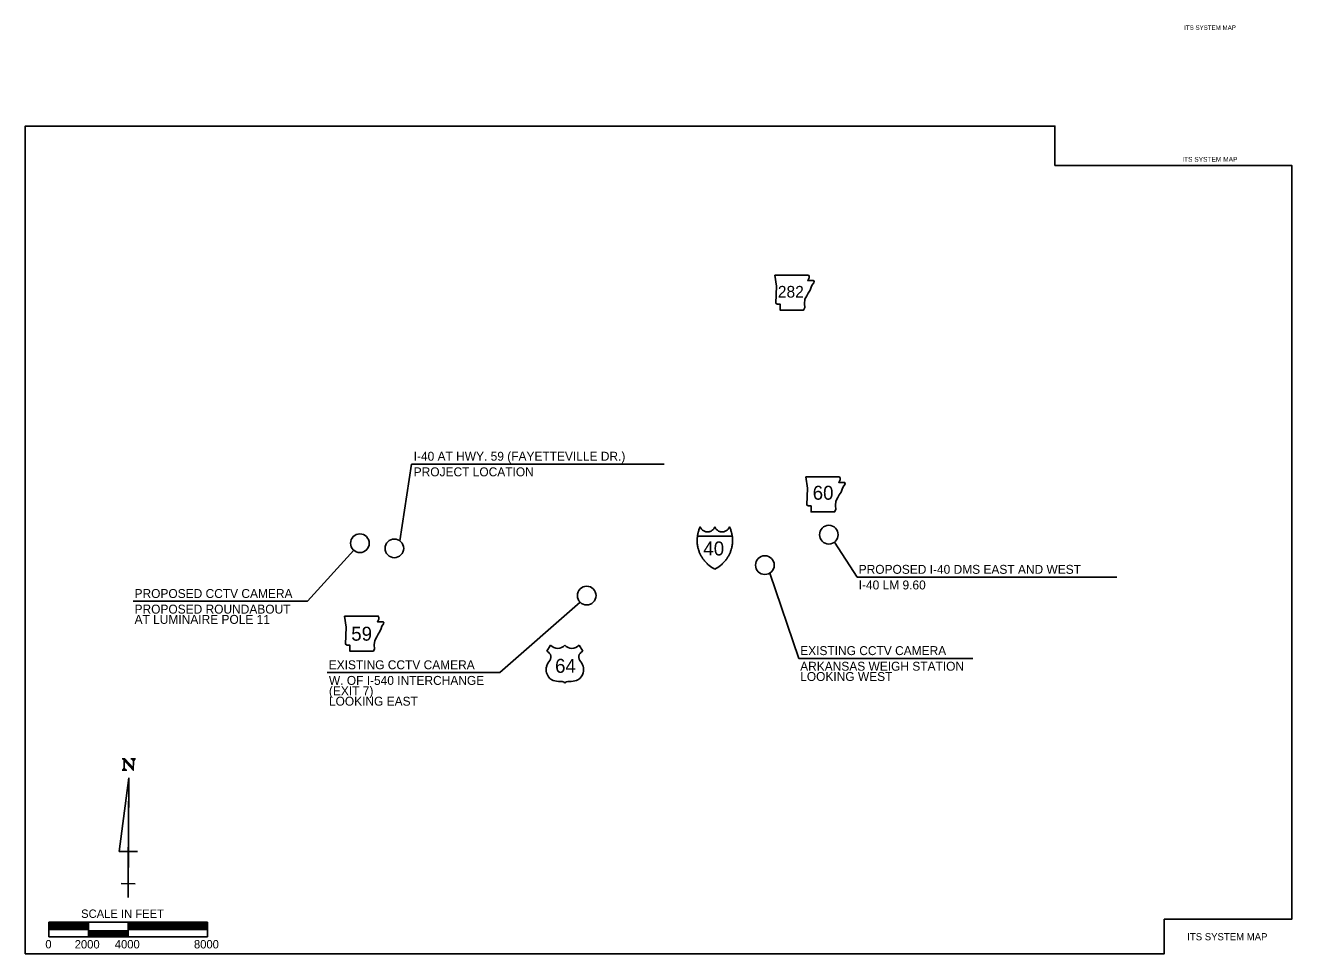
# Model space of a CAD drawing. Extents: x 164834 to 228648, y 1232466 to 1279237.
import ezdxf

# ---------------------------------------------------------------- set-up
doc = ezdxf.new("R2010")
doc.units = 0
for name, color, linetype in [('10', 7, 'Continuous'), ('G-ANNO-TEXT', 7, 'Continuous'), ('Level 1', 7, 'Continuous'), ('Level 21', 7, 'Continuous'), ('Level 22', 7, 'Continuous'), ('Level 23', 7, 'Continuous'), ('R_No Plot', 7, 'Continuous'), ('SCALE', 7, 'Continuous')]:
    doc.layers.add(name, color=color, linetype=linetype)

msp = doc.modelspace()

# ---------------------------------------------------------------- linework, layer by layer
at = {"layer": '10'}
for p, q in [((183699, 1253272), (184299, 1257133)), ((184287, 1257133), (197031, 1257133)), ((179045, 1250218), (181386, 1252788)), ((205603, 1253197), (206745, 1251435)), ((202352, 1251642), (203811, 1247341)), ((206745, 1251435), (219837, 1251436)), ((170268, 1250218), (179045, 1250218)), ((192794, 1250171), (188749, 1246626)), ((203811, 1247341), (212588, 1247341)), ((180049, 1246626), (188749, 1246626))]:
    msp.add_line(p, q, dxfattribs=at)
for centre in [(205324, 1253576), (181694, 1253144), (183430, 1252886), (202101, 1252040), (193123, 1250507)]:
    msp.add_circle(centre, 471, dxfattribs=at)
at = {"layer": 'Level 1'}
for p, q in [((170044, 1241326), (169562, 1237618)), ((170015, 1235296), (170044, 1241326)), ((170044, 1241326), (170021, 1236687)), ((169562, 1237618), (170490, 1237613)), ((170015, 1235296), (170021, 1236687)), ((170018, 1235992), (169670, 1235994)), ((169670, 1235994), (170366, 1235990)), ((170015, 1235296), (170018, 1235992))]:
    msp.add_line(p, q, dxfattribs=at)
for points in [[(169709, 1242277), (169848, 1242276), (170277, 1241807)], [(169819, 1242203), (169817, 1241809), (169750, 1241714)], [(169753, 1242276), (170276, 1241711), (170279, 1242179), (170345, 1242273)], [(169804, 1242276), (170276, 1241763)], [(169826, 1242276), (170277, 1241792)], [(170148, 1242274), (170389, 1242274)], [(170213, 1242274), (170279, 1242179), (170308, 1242274)], [(170279, 1242179), (170323, 1242274)], [(169706, 1241714), (169948, 1241713)], [(169817, 1241809), (169845, 1241714)], [(169860, 1241713), (169817, 1241809), (169875, 1241713)]]:
    msp.add_lwpolyline(points, dxfattribs=at)
at = {"layer": 'Level 21'}
for points in [[(202607, 1266658), (202691, 1266094), (202654, 1265239), (202729, 1265192), (202870, 1265192), (202870, 1264891), (204054, 1264891), (204110, 1265013), (204092, 1265211), (204120, 1265436), (204223, 1265615), (204289, 1265746), (204383, 1265887), (204439, 1266038), (204486, 1266160), (204571, 1266263), (204590, 1266329), (204552, 1266376), (204261, 1266376), (204327, 1266508), (204336, 1266592), (204297, 1266657)], [(204168, 1256490), (204253, 1255926), (204215, 1255071), (204291, 1255024), (204432, 1255024), (204432, 1254723), (205616, 1254723), (205672, 1254846), (205654, 1255043), (205682, 1255269), (205785, 1255447), (205851, 1255579), (205945, 1255720), (206001, 1255870), (206048, 1255992), (206133, 1256096), (206152, 1256161), (206114, 1256208), (205823, 1256208), (205888, 1256340), (205898, 1256425), (205859, 1256490)], [(180925, 1249472), (181009, 1248908), (180972, 1248053), (181047, 1248006), (181188, 1248006), (181188, 1247705), (182372, 1247705), (182429, 1247828), (182410, 1248025), (182438, 1248250), (182541, 1248429), (182607, 1248561), (182701, 1248702), (182758, 1248852), (182805, 1248974), (182889, 1249078), (182908, 1249143), (182870, 1249190), (182579, 1249190), (182645, 1249322), (182654, 1249407), (182615, 1249471)]]:
    msp.add_lwpolyline(points, close=True, dxfattribs=at)
at = {"layer": 'Level 22'}
for p, q in [((191306, 1248010), (191114, 1247712)), ((192736, 1248010), (192929, 1247712))]:
    msp.add_line(p, q, dxfattribs=at)
for centre, radius, start, end in [((190863, 1247281), 500, 30.7809, 59.98827), ((191665, 1248311), 468, 220.07504, 319.67012), ((192378, 1248311), 468, 220.32988, 319.92496), ((193180, 1247281), 500, 120.01173, 149.2191), ((191605, 1246776), 528, 160.95764, 197.38186), ((191868, 1246710), 799, 138.95648, 162.69135), ((190973, 1247412), 343, 328.81046, 21.21077), ((193070, 1247412), 343, 158.78923, 211.18954), ((192174, 1246710), 799, 17.30865, 41.04352), ((192438, 1246776), 528, 342.61814, 19.04236), ((191691, 1246777), 611, 195.10743, 237.13119), ((192352, 1246777), 611, 302.86881, 344.89257), ((191702, 1246970), 784, 244.07708, 269.57785), ((191720, 1244748), 1437, 81.19416, 90.95388), ((191900, 1246037), 138, 28.03422, 72.98637), ((192143, 1246037), 138, 107.01363, 151.96578), ((192323, 1244748), 1437, 89.04613, 98.80584), ((192341, 1246970), 784, 270.42215, 295.92292)]:
    msp.add_arc(centre, radius, start, end, dxfattribs=at)
at = {"layer": 'Level 23'}
for points in [[(198704, 1253505), (198710, 1253547), (198717, 1253584), (198727, 1253632), (198734, 1253663), (198743, 1253700), (198755, 1253743), (198767, 1253779), (198779, 1253817), (198796, 1253863), (198813, 1253906), (198827, 1253939), (198839, 1253966), (198852, 1253937), (198867, 1253910), (198883, 1253885), (198905, 1253858), (198922, 1253839), (198943, 1253819), (198964, 1253801), (198986, 1253785), (199023, 1253763), (199060, 1253746), (199094, 1253734), (199127, 1253725), (199163, 1253719), (199205, 1253716), (199232, 1253717), (199263, 1253720), (199291, 1253725), (199321, 1253732), (199351, 1253742), (199392, 1253760), (199420, 1253775), (199452, 1253798), (199483, 1253824), (199506, 1253847), (199532, 1253878), (199554, 1253910), (199566, 1253933), (199580, 1253963)], [(199580, 1253963), (199594, 1253933), (199606, 1253910), (199628, 1253878), (199654, 1253847), (199676, 1253824), (199708, 1253798), (199740, 1253775), (199768, 1253760), (199809, 1253742), (199839, 1253732), (199869, 1253725), (199897, 1253720), (199928, 1253717), (199955, 1253716), (199997, 1253719), (200033, 1253725), (200066, 1253734), (200100, 1253746), (200137, 1253763), (200173, 1253785), (200196, 1253801), (200217, 1253819), (200238, 1253839), (200255, 1253858), (200276, 1253885), (200293, 1253910), (200308, 1253937), (200321, 1253966), (200333, 1253939), (200347, 1253906), (200364, 1253863), (200381, 1253817), (200393, 1253779), (200404, 1253743), (200417, 1253700), (200426, 1253663), (200433, 1253632), (200443, 1253584), (200450, 1253547), (200456, 1253505)], [(199580, 1251845), (199503, 1251886), (199436, 1251927), (199361, 1251977), (199292, 1252030), (199216, 1252094), (199188, 1252120), (199156, 1252152), (199126, 1252183), (199093, 1252219), (199061, 1252256), (199034, 1252289), (199005, 1252327), (198979, 1252363), (198956, 1252396), (198936, 1252427), (198920, 1252454), (198898, 1252492), (198881, 1252522), (198862, 1252558), (198844, 1252595), (198828, 1252629), (198813, 1252662), (198798, 1252699), (198785, 1252734), (198773, 1252770), (198760, 1252807), (198749, 1252846), (198739, 1252882), (198730, 1252917), (198723, 1252948), (198718, 1252971), (198710, 1253016), (198702, 1253067), (198696, 1253110), (198692, 1253155), (198690, 1253192), (198688, 1253239), (198688, 1253282), (198689, 1253330), (198690, 1253362), (198692, 1253391), (198693, 1253409), (198698, 1253457), (198704, 1253505)], [(200456, 1253505), (198704, 1253505)], [(200456, 1253505), (200462, 1253457), (200467, 1253409), (200468, 1253391), (200470, 1253362), (200471, 1253330), (200472, 1253282), (200472, 1253239), (200470, 1253192), (200468, 1253155), (200464, 1253110), (200458, 1253067), (200450, 1253016), (200442, 1252971), (200437, 1252948), (200430, 1252917), (200421, 1252882), (200411, 1252846), (200400, 1252807), (200387, 1252770), (200375, 1252734), (200362, 1252699), (200347, 1252662), (200332, 1252629), (200316, 1252595), (200298, 1252558), (200279, 1252522), (200262, 1252492), (200240, 1252454), (200224, 1252427), (200204, 1252396), (200181, 1252363), (200154, 1252327), (200126, 1252289), (200099, 1252256), (200067, 1252219), (200034, 1252183), (200004, 1252152), (199972, 1252120), (199944, 1252094), (199868, 1252030), (199799, 1251977), (199724, 1251927), (199657, 1251886), (199580, 1251845)]]:
    msp.add_lwpolyline(points, dxfattribs=at)
at = {"layer": 'R_No Plot'}
msp.add_lwpolyline([(212824, 1232466), (208844, 1232466), (204625, 1232466), (164834, 1232466), (164834, 1274159), (216714, 1274159), (216714, 1272177), (228648, 1272177), (228648, 1263721), (228648, 1234197), (222229, 1234197), (222229, 1232466)], close=True, dxfattribs=at)
at = {"layer": 'SCALE'}
for p, q in [((166015, 1234045), (174015, 1234045)), ((166015, 1233322), (166015, 1234045)), ((166015, 1233985), (168015, 1233985)), ((166015, 1233925), (168015, 1233925)), ((166015, 1233864), (168015, 1233865)), ((166015, 1233804), (168015, 1233804)), ((166015, 1233744), (168015, 1233744)), ((168015, 1233683), (166015, 1233683)), ((168015, 1233322), (168015, 1234045)), ((168015, 1233623), (170015, 1233623)), ((168015, 1233563), (170015, 1233563)), ((170015, 1233322), (170015, 1234045)), ((170015, 1233985), (174015, 1233985)), ((170015, 1233925), (174015, 1233925)), ((170015, 1233865), (174015, 1233864)), ((170015, 1233804), (174015, 1233804)), ((170015, 1233744), (174015, 1233744)), ((170015, 1233683), (174015, 1233683)), ((174015, 1233322), (174015, 1234045)), ((166015, 1233322), (174015, 1233322)), ((166015, 1233322), (170015, 1233322)), ((166015, 1233322), (168015, 1233322)), ((168015, 1233503), (170015, 1233503)), ((168015, 1233442), (170015, 1233442)), ((168015, 1233382), (170015, 1233382))]:
    msp.add_line(p, q, dxfattribs=at)

# ---------------------------------------------------------------- texts
at = {"layer": '10'}
for s, p in [('I-40 AT HWY. 59 (FAYETTEVILLE DR.)', (184404, 1257302)), ('PROJECT LOCATION', (184404, 1256515)), ('PROPOSED I-40 DMS EAST AND WEST', (206829, 1251604)), ('PROPOSED CCTV CAMERA', (170339, 1250386)), ('I-40 LM 9.60', (206829, 1250817)), ('AT LUMINAIRE POLE 11', (170339, 1249083)), ('PROPOSED ROUNDABOUT', (170339, 1249599)), ('EXISTING CCTV CAMERA', (203882, 1247509)), ('EXISTING CCTV CAMERA', (180123, 1246795)), ('ARKANSAS WEIGH STATION', (203881, 1246722)), ('W. OF I-540 INTERCHANGE ', (180133, 1246008)), ('LOOKING WEST', (203881, 1246205)), ('(EXIT 7)', (180133, 1245484)), ('LOOKING EAST', (180133, 1244960))]:
    msp.add_text(s, height=450, rotation=0.00041, dxfattribs=at).set_placement(p)
at = {"layer": 'G-ANNO-TEXT'}
for height, rotation, p in [(224.89, 359.99878, (223231, 1279009)), (240, 360, (223134, 1272367)), (360, 360, (223387, 1233141))]:
    msp.add_text('ITS SYSTEM MAP', height=height, rotation=rotation, dxfattribs=at).set_placement(p)
at = {"layer": 'Level 21'}
for s, height, p in [('282', 586.7, (202755, 1265522)), ('60', 703.3, (204512, 1255336)), ('59', 703.3, (181258, 1248234))]:
    msp.add_text(s, height=height, dxfattribs=at).set_placement(p)
at = {"layer": 'Level 22'}
msp.add_text('64', height=703.3, dxfattribs=at).set_placement((191529, 1246615))
at = {"layer": 'Level 23'}
msp.add_text('40', height=705.8, dxfattribs=at).set_placement((198999, 1252528))
at = {"layer": 'SCALE'}
for s, height, p in [('SCALE IN FEET', 422.14, (167645, 1234268)), ('0', 422, (165843, 1232732)), ('2000', 422.1, (167323, 1232728)), ('4000', 422.1, (169343, 1232731)), ('8000', 422.1, (173332, 1232730))]:
    msp.add_text(s, height=height, rotation=0.00536, dxfattribs=at).set_placement(p)

doc.saveas('drawing.dxf')
